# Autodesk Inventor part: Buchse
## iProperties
Author: fuessel_t
Shininess: 20.0
Angle Display Precision: 2
Document Length Units: 11269
Document Angle Units: 11283
Document Time Units: 11279
Document Mass Units: 11290
Document Length Units Precision: 3
Document Angle Units Precision: 2
Compacted: False
PropertySet Name: _Private Model Information
Created: 2003-07
Part Number: Buchse
Material: Lexan (klar)
Document SubType Name: Modellieren
Designer: fuessel_t
Control State: 0
Master: False
Checked Out: False
PropertySet Name: Design Tracking Control
Density: 0.0
Volumn: 0.0
Area: 0.0
PropertySet Name: Model Information
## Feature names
1. Drehung1 [Revolution]
2. Spirale1
3. Bohrung1 [Hole]
